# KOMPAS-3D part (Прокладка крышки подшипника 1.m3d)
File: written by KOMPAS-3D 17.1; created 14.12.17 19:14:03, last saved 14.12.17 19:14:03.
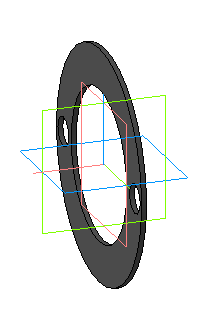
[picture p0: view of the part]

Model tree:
1. Операция без истории:1  (labels: Прокладка крышки подшипника 1)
